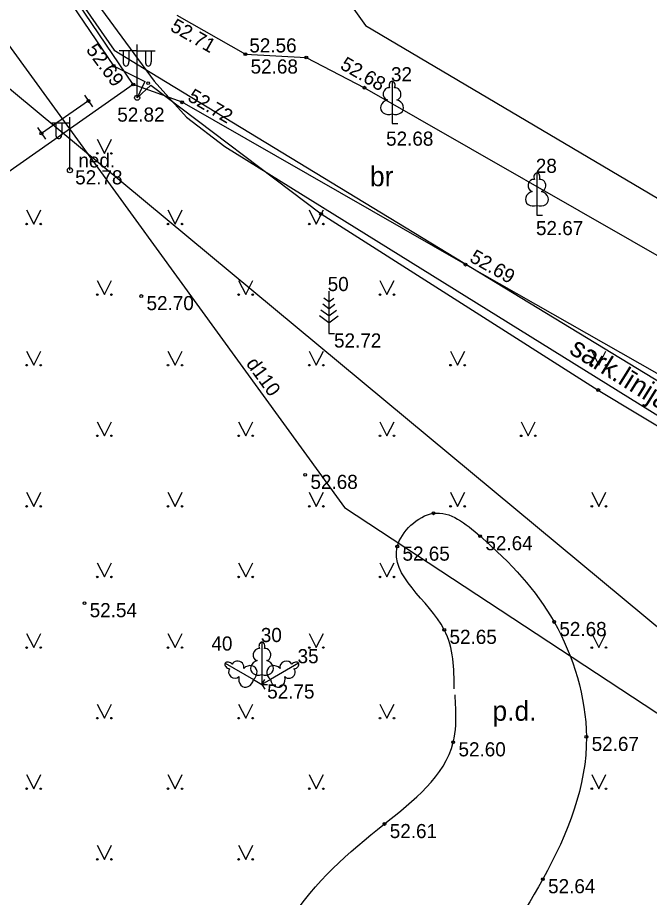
# Model space of a CAD drawing. Extents: x 619806 to 620082, y 405176 to 405386.
# Drawn here: x 620009.43 to 620031.79, y 405261.15 to 405292.31 of the extents above; entities that cross this region are included whole.
import ezdxf

# ---------------------------------------------------------------- set-up
doc = ezdxf.new("R2010")
doc.units = 0
for name, color, linetype in [('24', 7, 'Continuous'), ('APGR_SARK_####_####_#', 7, 'Continuous'), ('APGR_SARK_IZNL_TKST_#', 7, 'Continuous'), ('APGS_ELEM_####_####_#', 7, 'Continuous'), ('APGS_ELEM_####_TKST_#', 7, 'Continuous'), ('APGS_VADP_ZSPR_####_#', 7, 'Continuous'), ('BUVE_SOLS_####_####_#', 7, 'Continuous'), ('CELI_CAPM_####_####_#', 7, 'Continuous'), ('CELI_CMAL_####_####_#', 7, 'Continuous'), ('CELI_CSEG_####_TKST_#', 7, 'Continuous'), ('CELI_SEGL_####_####_#', 7, 'Continuous'), ('RAMI_UZMR_####_####_#', 7, 'Continuous'), ('RELJ_AATZ_####_TKST_#', 7, 'Continuous'), ('RELJ_ELEM_####_####_#', 7, 'Continuous'), ('ROBZ_UZMR_####_####_#', 7, 'Continuous'), ('SAKT_VADP_KABE_####_#', 7, 'Continuous'), ('TERT_DIAM_####_TKST_#', 7, 'Continuous'), ('TERT_ELEM_####_####_#', 7, 'Continuous'), ('TERT_IZMT_####_TKST_#', 7, 'Continuous'), ('TERT_KONT_####_####_#', 7, 'Continuous'), ('UDTK_VADP_UDEN_####_#', 7, 'Continuous'), ('UDTK_VADP_UDEN_TKST_#', 7, 'Continuous')]:
    doc.layers.add(name, color=color, linetype=linetype)

msp = doc.modelspace()

# ---------------------------------------------------------------- linework, layer by layer
at = {"layer": '24'}
msp.add_line((620012.847, 405291.155), (620014.119, 405290.38), dxfattribs=at)
at = {"layer": 'APGR_SARK_####_####_#'}
msp.add_lwpolyline([(619976.198, 405343.424), (619987.786, 405326.116), (620001.138, 405307.928), (620014.265, 405290.061), (620015.405, 405288.784), (620016.767, 405287.746), (620041.487, 405272.379), (619990.053, 405197.403), (619990.053, 405197.403)], dxfattribs=at)
at = {"layer": 'APGS_ELEM_####_####_#'}
for p, q in [((620013.66, 405291.139), (620013.025, 405291.134)), ((620013.16, 405291.135), (620013.16, 405290.743)), ((620013.37, 405291.137), (620013.37, 405290.743)), ((620013.66, 405289.472), (620013.66, 405291.355)), ((620013.66, 405291.139), (620014.295, 405291.134)), ((620013.95, 405291.137), (620013.95, 405290.743)), ((620014.16, 405291.135), (620014.16, 405290.743)), ((620011.281, 405286.904), (620011.281, 405288.787)), ((620011.281, 405288.571), (620010.646, 405288.566)), ((620010.781, 405288.567), (620010.781, 405288.175)), ((620010.991, 405288.569), (620010.991, 405288.175))]:
    msp.add_line(p, q, dxfattribs=at)
for centre in [(620013.66, 405289.472), (620011.281, 405286.904)]:
    msp.add_circle(centre, 0.09, dxfattribs=at)
for centre, major_axis, start_param, end_param in [((620013.265, 405290.743), (0, 0.151), 1.570796, 4.712389), ((620014.055, 405290.743), (0, -0.151), 4.712389, 7.853982), ((620010.886, 405288.175), (0, 0.151), 1.570796, 4.712389)]:
    msp.add_ellipse(centre, major_axis=major_axis, ratio=0.695971, start_param=start_param, end_param=end_param, dxfattribs=at)
at = {"layer": 'APGS_VADP_ZSPR_####_#'}
msp.add_lwpolyline([(619990.647, 405321.492), (619992.044, 405320.41), (619998.442, 405311.177), (620006.316, 405300.184), (620012.827, 405290.604), (620013.926, 405290.046), (620013.66, 405289.472), (620014.139, 405289.916), (620020.167, 405285.36), (620029.979, 405279.119), (620034.093, 405276.637), (620034.718, 405277.157), (620034.581, 405276.433), (620041.718, 405272.423), (620046.265, 405269.109)], dxfattribs=at)
at = {"layer": 'BUVE_SOLS_####_####_#'}
for p, q in [((620011.795, 405289.564), (620012.079, 405289.152)), ((620010.129, 405288.415), (620010.413, 405288.003))]:
    msp.add_line(p, q, dxfattribs=at)
msp.add_lwpolyline([(620011.937, 405289.358), (620010.271, 405288.209)], dxfattribs=at)
at = {"layer": 'CELI_CAPM_####_####_#'}
msp.add_lwpolyline([(620015.066, 405292.395), (620017.489, 405291.013), (620019.645, 405290.895), (620021.702, 405289.826), (620033.044, 405283.335), (620041.336, 405278.607), (620045.71, 405276.047), (620045.451, 405275.586), (620046.08, 405275.258), (620046.363, 405275.764), (620046.931, 405275.406), (620047.659, 405274.561), (620048.206, 405273.573), (620048.444, 405272.838)], dxfattribs=at)
at = {"layer": 'CELI_CMAL_####_####_#'}
msp.add_lwpolyline([(620044.255, 405272.554), (620043.092, 405273.429), (620033.269, 405279.026), (620025.28, 405283.562), (620015.248, 405289.312), (620013.524, 405289.938), (620004.396, 405283.537), (619995.598, 405277.461), (619983.971, 405269.299), (619977.275, 405264.531), (619978.155, 405255.368), (619978.832, 405249.941), (619981.369, 405226.774)], dxfattribs=at)
at = {"layer": 'CELI_SEGL_####_####_#'}
msp.add_lwpolyline([(620013.524, 405289.938), (620008.624, 405297.164), (620001.476, 405307.535), (619994.548, 405317.437), (619991.854, 405321.355)], dxfattribs=at)
at = {"layer": 'RAMI_UZMR_####_####_#'}
msp.add_lwpolyline([(619874.687, 405324.979), (619926.719, 405349.544), (619966.669, 405369.042), (620021.738, 405292.03), (620049.703, 405275.476), (620026.189, 405242.287), (620012.147, 405222.917), (619996.603, 405200.928), (619989.997, 405199.173), (619982.328, 405199.155), (619922.669, 405233.014), (619882.137, 405255.756), (619859.084, 405268.056), (619820.646, 405290.715), (619813.744, 405295.206), (619820.645, 405298.752)], close=True, dxfattribs=at)
at = {"layer": 'RELJ_ELEM_####_####_#'}
for centre in [(620017.489, 405291.013), (620019.645, 405290.895), (620012.827, 405290.604), (620013.524, 405289.938), (620014.049, 405289.987), (620021.702, 405289.826), (620011.937, 405289.358), (620015.248, 405289.312), (620010.271, 405288.209), (620020.167, 405285.36), (620025.28, 405283.562), (620013.806, 405282.449), (620029.979, 405279.119), (620019.607, 405276.118), (620024.144, 405274.754), (620025.797, 405273.946), (620022.864, 405273.577), (620011.794, 405271.575), (620028.415, 405270.906), (620024.528, 405270.63), (620029.557, 405266.838), (620024.845, 405266.647), (620022.413, 405263.752), (620028.016, 405261.799)]:
    msp.add_circle(centre, 0.05, dxfattribs=at)
at = {"layer": 'ROBZ_UZMR_####_####_#'}
for p, q in [((619991.921, 405321.247), (620012.847, 405291.155)), ((620014.119, 405290.38), (620044.084, 405272.127))]:
    msp.add_line(p, q, dxfattribs=at)
at = {"layer": 'SAKT_VADP_KABE_####_#'}
msp.add_lwpolyline([(619935.629, 405357.201), (619939.538, 405347.363), (619973.032, 405319.457), (620006.975, 405291.595), (620036.262, 405267.248), (620043.553, 405261.241)], dxfattribs=at)
at = {"layer": 'TERT_ELEM_####_####_#'}
for p, q in [((620022.681, 405288.901), (620022.681, 405288.554)), ((620022.681, 405288.554), (620022.881, 405288.554)), ((620012.25, 405288), (620012.5, 405287.5)), ((620012.5, 405287.5), (620012.75, 405288)), ((620009.75, 405285.5), (620010, 405285)), ((620010, 405285), (620010.25, 405285.5)), ((620014.75, 405285.5), (620015, 405285)), ((620015, 405285), (620015.25, 405285.5)), ((620019.75, 405285.5), (620020, 405285)), ((620020, 405285), (620020.25, 405285.5)), ((620027.806, 405285.659), (620027.806, 405285.312)), ((620027.806, 405285.312), (620028.006, 405285.312)), ((620012.25, 405283), (620012.5, 405282.5)), ((620012.5, 405282.5), (620012.75, 405283)), ((620017.25, 405283), (620017.5, 405282.5)), ((620017.5, 405282.5), (620017.75, 405283)), ((620022.25, 405283), (620022.5, 405282.5)), ((620022.5, 405282.5), (620022.75, 405283)), ((620020.441, 405282.249), (620020.265, 405282.377)), ((620020.441, 405282.625), (620020.441, 405281.125)), ((620020.441, 405282.249), (620020.615, 405282.377)), ((620020.441, 405281.999), (620020.225, 405282.157)), ((620020.441, 405281.999), (620020.657, 405282.157)), ((620020.441, 405281.749), (620020.163, 405281.953)), ((620020.441, 405281.749), (620020.719, 405281.953)), ((620020.441, 405281.499), (620020.109, 405281.743)), ((620020.441, 405281.499), (620020.775, 405281.743)), ((620020.441, 405281.125), (620020.641, 405281.125)), ((620009.75, 405280.5), (620010, 405280)), ((620010, 405280), (620010.25, 405280.5)), ((620014.75, 405280.5), (620015, 405280)), ((620015, 405280), (620015.25, 405280.5)), ((620019.75, 405280.5), (620020, 405280)), ((620020, 405280), (620020.25, 405280.5)), ((620024.75, 405280.5), (620025, 405280)), ((620025, 405280), (620025.25, 405280.5)), ((620029.75, 405280.5), (620030, 405280)), ((620030, 405280), (620030.25, 405280.5)), ((620012.25, 405278), (620012.5, 405277.5)), ((620012.5, 405277.5), (620012.75, 405278)), ((620017.25, 405278), (620017.5, 405277.5)), ((620017.5, 405277.5), (620017.75, 405278)), ((620022.25, 405278), (620022.5, 405277.5)), ((620022.5, 405277.5), (620022.75, 405278)), ((620027.25, 405278), (620027.5, 405277.5)), ((620027.5, 405277.5), (620027.75, 405278)), ((620009.75, 405275.5), (620010, 405275)), ((620010, 405275), (620010.25, 405275.5)), ((620014.75, 405275.5), (620015, 405275)), ((620015, 405275), (620015.25, 405275.5)), ((620019.75, 405275.5), (620020, 405275)), ((620020, 405275), (620020.25, 405275.5)), ((620024.75, 405275.5), (620025, 405275)), ((620025, 405275), (620025.25, 405275.5)), ((620029.75, 405275.5), (620030, 405275)), ((620030, 405275), (620030.25, 405275.5)), ((620012.25, 405273), (620012.5, 405272.5)), ((620012.5, 405272.5), (620012.75, 405273)), ((620017.25, 405273), (620017.5, 405272.5)), ((620017.5, 405272.5), (620017.75, 405273)), ((620022.25, 405273), (620022.5, 405272.5)), ((620022.5, 405272.5), (620022.75, 405273)), ((620009.75, 405270.5), (620010, 405270)), ((620010, 405270), (620010.25, 405270.5)), ((620014.75, 405270.5), (620015, 405270)), ((620015, 405270), (620015.25, 405270.5)), ((620019.75, 405270.5), (620020, 405270)), ((620020, 405270), (620020.25, 405270.5)), ((620029.75, 405270.5), (620030, 405270)), ((620030, 405270), (620030.25, 405270.5)), ((620018.076, 405269.042), (620018.076, 405268.695)), ((620017.775, 405268.868), (620018.076, 405268.695)), ((620018.076, 405268.695), (620018.176, 405268.868)), ((620018.377, 405268.868), (620018.076, 405268.695)), ((620018.076, 405268.695), (620018.276, 405268.695)), ((620018.076, 405268.695), (620018.176, 405268.522)), ((620012.25, 405268), (620012.5, 405267.5)), ((620012.5, 405267.5), (620012.75, 405268)), ((620017.25, 405268), (620017.5, 405267.5)), ((620017.5, 405267.5), (620017.75, 405268)), ((620022.25, 405268), (620022.5, 405267.5)), ((620022.5, 405267.5), (620022.75, 405268)), ((620009.75, 405265.5), (620010, 405265)), ((620010, 405265), (620010.25, 405265.5)), ((620014.75, 405265.5), (620015, 405265)), ((620015, 405265), (620015.25, 405265.5)), ((620019.75, 405265.5), (620020, 405265)), ((620020, 405265), (620020.25, 405265.5)), ((620029.75, 405265.5), (620030, 405265)), ((620030, 405265), (620030.25, 405265.5)), ((620012.25, 405263), (620012.5, 405262.5)), ((620012.5, 405262.5), (620012.75, 405263)), ((620017.25, 405263), (620017.5, 405262.5)), ((620017.5, 405262.5), (620017.75, 405263))]:
    msp.add_line(p, q, dxfattribs=at)
for points in [[(620022.681, 405290.054), (620022.681, 405288.901)], [(620022.771, 405289.822), (620022.77, 405289.823)], [(620027.806, 405286.812), (620027.806, 405285.659)], [(620027.896, 405286.58), (620027.895, 405286.581)], [(620018.076, 405270.195), (620018.076, 405269.042)], [(620018.166, 405269.963), (620018.165, 405269.964)], [(620016.777, 405269.445), (620017.775, 405268.868)], [(620017.023, 405269.406), (620017.022, 405269.406)], [(620019.375, 405269.445), (620018.377, 405268.868)], [(620019.219, 405269.251), (620019.219, 405269.253)]]:
    msp.add_lwpolyline(points, dxfattribs=at)
for centre, radius in [((620012.25, 405287.5), 0.028), ((620012.75, 405287.5), 0.0263), ((620009.75, 405285), 0.028), ((620010.25, 405285), 0.0263), ((620014.75, 405285), 0.028), ((620015.25, 405285), 0.0263), ((620019.75, 405285), 0.028), ((620020.25, 405285), 0.0263), ((620012.25, 405282.5), 0.028), ((620012.75, 405282.5), 0.0263), ((620017.25, 405282.5), 0.028), ((620017.75, 405282.5), 0.0263), ((620022.25, 405282.5), 0.028), ((620022.75, 405282.5), 0.0263), ((620009.75, 405280), 0.028), ((620010.25, 405280), 0.0263), ((620014.75, 405280), 0.028), ((620015.25, 405280), 0.0263), ((620019.75, 405280), 0.028), ((620020.25, 405280), 0.0263), ((620024.75, 405280), 0.028), ((620025.25, 405280), 0.0263), ((620029.75, 405280), 0.028), ((620030.25, 405280), 0.0263), ((620012.25, 405277.5), 0.028), ((620012.75, 405277.5), 0.0263), ((620017.25, 405277.5), 0.028), ((620017.75, 405277.5), 0.0263), ((620022.25, 405277.5), 0.028), ((620022.75, 405277.5), 0.0263), ((620027.25, 405277.5), 0.028), ((620027.75, 405277.5), 0.0263), ((620009.75, 405275), 0.028), ((620010.25, 405275), 0.0263), ((620014.75, 405275), 0.028), ((620015.25, 405275), 0.0263), ((620019.75, 405275), 0.028), ((620020.25, 405275), 0.0263), ((620024.75, 405275), 0.028), ((620025.25, 405275), 0.0263), ((620029.75, 405275), 0.028), ((620030.25, 405275), 0.0263), ((620012.25, 405272.5), 0.028), ((620012.75, 405272.5), 0.0263), ((620017.25, 405272.5), 0.028), ((620017.75, 405272.5), 0.0263), ((620022.25, 405272.5), 0.028), ((620022.75, 405272.5), 0.0263), ((620009.75, 405270), 0.028), ((620010.25, 405270), 0.0263), ((620014.75, 405270), 0.028), ((620015.25, 405270), 0.0263), ((620019.75, 405270), 0.028), ((620020.25, 405270), 0.0263), ((620029.75, 405270), 0.028), ((620030.25, 405270), 0.0263), ((620012.25, 405267.5), 0.028), ((620012.75, 405267.5), 0.0263), ((620017.25, 405267.5), 0.028), ((620017.75, 405267.5), 0.0263), ((620022.25, 405267.5), 0.028), ((620022.75, 405267.5), 0.0263), ((620009.75, 405265), 0.028), ((620010.25, 405265), 0.0263), ((620014.75, 405265), 0.028), ((620015.25, 405265), 0.0263), ((620019.75, 405265), 0.028), ((620020.25, 405265), 0.0263), ((620029.75, 405265), 0.028), ((620030.25, 405265), 0.0263), ((620012.25, 405262.5), 0.028), ((620012.75, 405262.5), 0.0263), ((620017.25, 405262.5), 0.028), ((620017.75, 405262.5), 0.0263)]:
    msp.add_circle(centre, radius, dxfattribs=at)
for centre, major_axis, ratio, start_param, end_param in [((620022.681, 405289.904), (0, -0.15), 0.707107, 3.14537, 5.287485), ((620022.681, 405289.904), (0, -0.15), 0.707107, 0.995701, 3.137816), ((620022.553, 405289.609), (-0.039, -0.212), 0.861323, 3.141593, 6.283185), ((620022.809, 405289.609), (0.039, -0.212), 0.861323, 0, 3.141593), ((620022.591, 405289.147), (0.307, 0.095), 0.814445, 1.570796, 4.752015), ((620022.771, 405289.147), (-0.307, 0.095), 0.814445, 1.531171, 4.712389), ((620027.806, 405286.662), (0, -0.15), 0.707107, 3.14537, 5.287485), ((620027.806, 405286.662), (0, -0.15), 0.707107, 0.995701, 3.137816), ((620027.678, 405286.367), (-0.039, -0.212), 0.861323, 3.141593, 6.283185), ((620027.934, 405286.367), (0.039, -0.212), 0.861323, 0, 3.141593), ((620027.716, 405285.905), (0.307, 0.095), 0.814445, 1.570796, 4.752015), ((620027.896, 405285.905), (-0.307, 0.095), 0.814445, 1.531171, 4.712389), ((620017.948, 405269.75), (-0.039, -0.212), 0.861323, 3.141593, 6.283185), ((620018.076, 405270.045), (0, -0.15), 0.707107, 3.14537, 5.287485), ((620018.076, 405270.045), (0, -0.15), 0.707107, 0.995701, 3.137816), ((620018.204, 405269.75), (0.039, -0.212), 0.861323, 0, 3.141593), ((620016.907, 405269.37), (0.13, -0.075), 0.707107, 3.14537, 5.287485), ((620016.907, 405269.37), (0.13, -0.075), 0.707107, 0.995701, 3.137816), ((620017.226, 405269.334), (0.203, -0.073), 0.861323, 0, 3.141593), ((620017.607, 405269.069), (-0.236, -0.218), 0.814445, 1.531171, 4.712389), ((620017.986, 405269.288), (0.307, 0.095), 0.814445, 1.570796, 4.752015), ((620018.166, 405269.288), (-0.307, 0.095), 0.814445, 1.531171, 4.712389), ((620018.545, 405269.069), (0.236, -0.218), 0.814445, 1.570796, 4.752015), ((620018.926, 405269.334), (-0.203, -0.073), 0.861323, 3.141593, 6.283185), ((620019.245, 405269.37), (-0.13, -0.075), 0.707107, 3.14537, 5.287485), ((620019.245, 405269.37), (-0.13, -0.075), 0.707107, 0.995701, 3.137816), ((620017.098, 405269.111), (0.165, -0.14), 0.861323, 3.141593, 6.283185), ((620019.054, 405269.111), (-0.165, -0.14), 0.861323, 0, 3.141593), ((620017.518, 405268.914), (0.071, 0.313), 0.814445, 1.570796, 4.752015), ((620018.634, 405268.914), (-0.071, 0.313), 0.814445, 1.531171, 4.712389)]:
    msp.add_ellipse(centre, major_axis=major_axis, ratio=ratio, start_param=start_param, end_param=end_param, dxfattribs=at)
at = {"layer": 'TERT_KONT_####_####_#'}
msp.add_spline([(620024.879, 405268.534), (620024.528, 405270.63), (620022.864, 405273.577), (620024.144, 405274.754), (620025.797, 405273.946), (620028.415, 405270.906), (620029.557, 405266.838), (620028.016, 405261.799), (620024.855, 405258.401), (620021.99, 405257.291), (620019.533, 405254.622), (620018.543, 405255.26), (620019.037, 405260.269), (620022.413, 405263.752), (620024.845, 405266.647), (620024.934, 405267.871), (620024.91, 405268.33)], degree=3, dxfattribs=at)
at = {"layer": 'UDTK_VADP_UDEN_####_#'}
msp.add_lwpolyline([(620006.936, 405294.332), (620021.003, 405274.963), (620032.468, 405267.412)], dxfattribs=at)

# ---------------------------------------------------------------- texts
at = {"layer": 'APGR_SARK_IZNL_TKST_#'}
msp.add_text('sark.līnija', height=0.7, rotation=328.134, dxfattribs=at).set_placement((620028.914, 405280.442))
at = {"layer": 'APGS_ELEM_####_TKST_#'}
msp.add_text('ned.', height=0.5, dxfattribs=at).set_placement((620011.579, 405287.003))
at = {"layer": 'CELI_CSEG_####_TKST_#'}
msp.add_text('br', height=0.7, dxfattribs=at).set_placement((620021.898, 405286.339))
at = {"layer": 'RELJ_AATZ_####_TKST_#'}
for s, rotation, p in [(' 52.71', 330.301, (620014.634, 405291.961)), (' 52.69', 306.448, (620011.721, 405291.311)), (' 52.68', 330.2176, (620020.648, 405290.611)), (' 52.72', 329.3854, (620015.251, 405289.488)), (' 52.69', 330.4129, (620025.226, 405283.785))]:
    msp.add_text(s, height=0.5, rotation=rotation, dxfattribs=at).set_placement(p)
for s, p in [(' 52.56', (620017.444, 405291.076)), (' 52.68', (620017.489, 405290.328)), (' 52.82', (620012.771, 405288.625)), (' 52.68', (620022.283, 405287.774)), (' 52.78', (620011.281, 405286.404)), (' 52.67', (620027.587, 405284.606)), (' 52.70', (620013.806, 405281.949)), (' 52.72', (620020.441, 405280.625)), (' 52.68', (620019.607, 405275.618)), (' 52.64', (620025.797, 405273.446)), (' 52.65', (620022.864, 405273.077)), (' 52.54', (620011.794, 405271.075)), (' 52.68', (620028.415, 405270.406)), (' 52.65', (620024.528, 405270.13)), (' 52.75', (620018.076, 405268.195)), (' 52.67', (620029.557, 405266.338)), (' 52.60', (620024.845, 405266.147)), (' 52.61', (620022.413, 405263.252)), (' 52.64', (620028.016, 405261.299))]:
    msp.add_text(s, height=0.5, dxfattribs=at).set_placement(p)
at = {"layer": 'TERT_DIAM_####_TKST_#'}
for s, p in [(' 32', (620022.456, 405290.054)), (' 28', (620027.581, 405286.812)), (' 50', (620020.216, 405282.625)), (' 30', (620017.851, 405270.195)), (' 40', (620016.102, 405269.895)), (' 35', (620019.151, 405269.445))]:
    msp.add_text(s, height=0.5, dxfattribs=at).set_placement(p)
at = {"layer": 'TERT_IZMT_####_TKST_#'}
msp.add_text('p.d.', height=0.7, dxfattribs=at).set_placement((620026.232, 405267.407))
at = {"layer": 'UDTK_VADP_UDEN_TKST_#'}
msp.add_text('d110', height=0.5, rotation=305.9895, dxfattribs=at).set_placement((620017.492, 405280.052))

doc.saveas('drawing.dxf')
